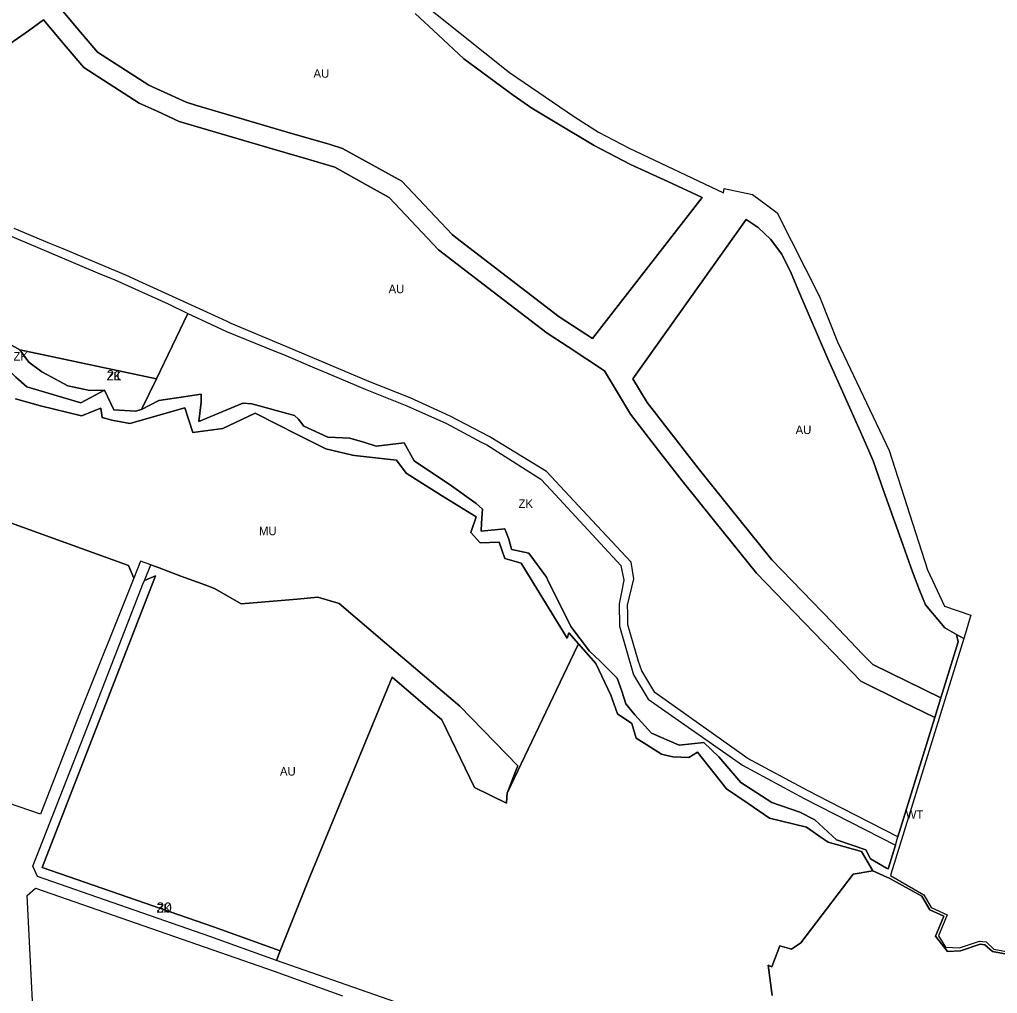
# Model space of a CAD drawing. Extents: x -522079 to -518833, y -1142398 to -1139961.
# Drawn here: x -520015 to -519439, y -1141329 to -1140756 of the extents above; entities that cross this region are included whole.
import ezdxf

# ---------------------------------------------------------------- set-up
doc = ezdxf.new("R2010")
doc.units = 0
for name, color, linetype in [('90640013', 7, 'Continuous'), ('90710013', 7, 'Continuous'), ('90710023', 7, 'Continuous'), ('90730013', 7, 'Continuous'), ('90750013', 7, 'Continuous'), ('90770013', 7, 'Continuous'), ('90830013', 7, 'Continuous'), ('ID_navrh', 7, 'Continuous')]:
    doc.layers.add(name, color=color, linetype=linetype)

msp = doc.modelspace()

# ---------------------------------------------------------------- linework, layer by layer
at = {"layer": '90640013'}
for points in [[(-520017.69, -1140966.19), (-520011.16, -1140971.75), (-519979.37, -1140981.19), (-519965.47, -1140973.69), (-519959.93, -1140985.31), (-519947.03, -1140986.05), (-519943.51, -1140985.08), (-519933.4, -1140979.93), (-519918.88, -1140977.69), (-519908.41, -1140976.07), (-519908.53, -1140980.82), (-519909.8, -1140992.3), (-519883.85, -1140981.36), (-519878.53, -1140981.83), (-519853.55, -1140988.6), (-519851.21, -1140990.81), (-519847.96, -1140994.97), (-519833.92, -1141001.35), (-519825.01, -1141001.81), (-519820.93, -1141002.11), (-519812.07, -1141004.64), (-519805.33, -1141006.69), (-519788.8, -1141004.86), (-519783.07, -1141015.31), (-519761.05, -1141030.01), (-519746.47, -1141040.52), (-519742.77, -1141043.74), (-519743.3, -1141051.84), (-519743.63, -1141056.81), (-519729.57, -1141055.46), (-519727.24, -1141061.4), (-519725.71, -1141067.43), (-519725.48, -1141067.48), (-519715.52, -1141069.7), (-519705.02, -1141083.87), (-519704.67, -1141084.75), (-519704.33, -1141085.64), (-519690.7, -1141113), (-519679.71, -1141127.39), (-519673.55, -1141133.3), (-519663.4, -1141143.35), (-519660.65, -1141151.03), (-519658.41, -1141158.35), (-519653.03, -1141164.92), (-519643.13, -1141175.65), (-519626.9, -1141182.72), (-519612.48, -1141181.23), (-519603.54, -1141189.56), (-519590.58, -1141204.82), (-519572.33, -1141216.46), (-519555.86, -1141222.18), (-519546.94, -1141226.78), (-519534.2, -1141238.58), (-519516.96, -1141244.4), (-519514.28, -1141249.74), (-519504.82, -1141255.11), (-519503.9, -1141255.56), (-519499.59, -1141241.58), (-519498.1, -1141236.79), (-519476.38, -1141166.58), (-519472.79, -1141154.97), (-519462.56, -1141121.92), (-519463.51, -1141117.64), (-519459.37, -1141120.07), (-519501.33, -1141255.67), (-519501.64, -1141256.67), (-519502.46, -1141259.44), (-519482.78, -1141270.88), (-519478.58, -1141278.28), (-519469.18, -1141282.65), (-519474.2, -1141295.1), (-519470.14, -1141301.74), (-519461.74, -1141302), (-519449.98, -1141298.09), (-519446.22, -1141298.48), (-519441.7, -1141302.87), (-519430.99, -1141304.77)], [(-519431.85, -1141306.14), (-519442.41, -1141304.27), (-519446.9, -1141300.29), (-519449.71, -1141299.98), (-519461.31, -1141303.85), (-519468.94, -1141304.33), (-519475.87, -1141295.24), (-519471.1, -1141283.41), (-519479.21, -1141279.64), (-519484.08, -1141271.62), (-519502.94, -1141261.24), (-519512.96, -1141256.69), (-519519.64, -1141245.38), (-519539.27, -1141239.84), (-519542.77, -1141237.45), (-519552.03, -1141231.12), (-519573.7, -1141225.77), (-519586.25, -1141217.21), (-519599.05, -1141208.49), (-519616.23, -1141186.99), (-519621.3, -1141190.09), (-519630.7, -1141189.62), (-519635, -1141188.59), (-519637.37, -1141188.02), (-519646.01, -1141182.51), (-519652.19, -1141178.57), (-519654.81, -1141169.94), (-519663.19, -1141164.28), (-519667.13, -1141153.28), (-519676.06, -1141134.77), (-519686.19, -1141123.12), (-519691.83, -1141116.63), (-519692.8, -1141119.72), (-519719.95, -1141075.61), (-519729.51, -1141072.8), (-519732.93, -1141063.24), (-519744.08, -1141063.56), (-519749.67, -1141057.47), (-519746.51, -1141048.43), (-519766.87, -1141035.85), (-519787.79, -1141022.58), (-519793.36, -1141014.98), (-519818.09, -1141012.26), (-519819.26, -1141011.99), (-519835.08, -1141008.27), (-519851.59, -1141000.07), (-519876.6, -1140987.29), (-519895.77, -1140996.31), (-519913.39, -1140998.68), (-519918.04, -1140984.12), (-519950.36, -1140993.42), (-519961.08, -1140991.39), (-519966.67, -1140989.91), (-519967.54, -1140984.38), (-519978.85, -1140988.86), (-520003.11, -1140982.94), (-520017.73, -1140978.78)]]:
    msp.add_lwpolyline(points, dxfattribs=at)
at = {"layer": '90710013'}
for points in [[(-519783.91, -1140740.96), (-519726.89, -1140786.75), (-519688.67, -1140812.79), (-519674.4, -1140821.79), (-519656.36, -1140831.22), (-519600.86, -1140857.49), (-519600.42, -1140854.95), (-519583.72, -1140858.5), (-519575.54, -1140864.6), (-519569.14, -1140869.38), (-519544.31, -1140918.54), (-519533.66, -1140945.39), (-519503.31, -1141009.21), (-519480.71, -1141079.48), (-519470.66, -1141100.87), (-519455.06, -1141106.14), (-519456.05, -1141109.33), (-519457.77, -1141114.91), (-519459.37, -1141120.07), (-519463.51, -1141117.64), (-519470.4, -1141113.6), (-519481.95, -1141100.21), (-519485.33, -1141091.52), (-519489.53, -1141080.75), (-519497.19, -1141059.15), (-519506.32, -1141033.4), (-519512.69, -1141015.45), (-519518.48, -1141001.84), (-519530.67, -1140974.63), (-519539.28, -1140955.41), (-519556.41, -1140915.6), (-519561.03, -1140904.86), (-519566.48, -1140893.71), (-519573.15, -1140884.93), (-519580.34, -1140878), (-519587.52, -1140873.31), (-519654.13, -1140967.02), (-519645.74, -1140981.03), (-519632.87, -1140997.67), (-519615.79, -1141019.75), (-519597.55, -1141042.38), (-519572.39, -1141073.59), (-519536.59, -1141110.65), (-519518.89, -1141129.28), (-519512.81, -1141135.27), (-519472.79, -1141154.97), (-519476.38, -1141166.58), (-519495.79, -1141157.02), (-519519.99, -1141145.11), (-519536.28, -1141128.25), (-519581.39, -1141081.54), (-519605.96, -1141051.06), (-519625.22, -1141027.17), (-519639.1, -1141009.23), (-519655.67, -1140987.81), (-519670.91, -1140962.34), (-519692.38, -1140948.3), (-519704.63, -1140940.29), (-519736.43, -1140915.9), (-519768.72, -1140891.13), (-519797.7, -1140860.26), (-519815.37, -1140850.5), (-519829.78, -1140842.53), (-519845.71, -1140837.84), (-519865.19, -1140832.11), (-519914.69, -1140817.53), (-519921.41, -1140815.55), (-519934.39, -1140809.6), (-519944.96, -1140804.75), (-519977.56, -1140783.82), (-519987.93, -1140771.54), (-520001.24, -1140755.77), (-520010.06, -1140762.16), (-520068.52, -1140802.68)], [(-519991.87, -1140748.27), (-519981.63, -1140760.4), (-519969.55, -1140774.7), (-519939.19, -1140794.19), (-519934.47, -1140796.36), (-519917.19, -1140804.28), (-519911.71, -1140805.9), (-519857.7, -1140821.8), (-519832.56, -1140829.21), (-519825.13, -1140831.39), (-519790.25, -1140850.67), (-519760.64, -1140882.2), (-519758.42, -1140883.91), (-519697.68, -1140930.5), (-519678.04, -1140943.34), (-519613.39, -1140860.38), (-519633.63, -1140850.83), (-519655.55, -1140840.89), (-519677.02, -1140829.78), (-519698.98, -1140816.54), (-519713.71, -1140807.66), (-519724.7, -1140800.07), (-519753.73, -1140778.67), (-519768.84, -1140764.57), (-519782.42, -1140752.04)]]:
    msp.add_lwpolyline(points, dxfattribs=at)
for points in [[(-519943.51, -1140985.08), (-519934.8, -1140967.08), (-519916.21, -1140928.63), (-519914.16, -1140929.63), (-519893.61, -1140939.25), (-519865.12, -1140950.76), (-519859.94, -1140952.86), (-519841.67, -1140960.58), (-519832.3, -1140964.53), (-519811.83, -1140973.18), (-519787.36, -1140982.97), (-519764.04, -1140993.49), (-519743.47, -1141004.35), (-519740.29, -1141006.03), (-519708.41, -1141026.12), (-519702.3, -1141032.7), (-519661.22, -1141076.98), (-519659.49, -1141085.69), (-519660.92, -1141092.62), (-519662.35, -1141099.54), (-519662.06, -1141112.71), (-519653.82, -1141141.35), (-519645.14, -1141155.67), (-519589.6, -1141194.6), (-519553.27, -1141214.2), (-519499.59, -1141241.58), (-519503.9, -1141255.56), (-519504.82, -1141255.11), (-519514.28, -1141249.74), (-519516.96, -1141244.4), (-519534.2, -1141238.58), (-519546.94, -1141226.78), (-519555.86, -1141222.18), (-519572.33, -1141216.46), (-519590.58, -1141204.82), (-519603.54, -1141189.56), (-519612.48, -1141181.23), (-519626.9, -1141182.72), (-519643.13, -1141175.65), (-519653.03, -1141164.92), (-519658.41, -1141158.35), (-519660.65, -1141151.03), (-519663.4, -1141143.35), (-519673.55, -1141133.3), (-519679.71, -1141127.39), (-519690.7, -1141113), (-519704.33, -1141085.64), (-519704.67, -1141084.75), (-519705.02, -1141083.87), (-519715.52, -1141069.7), (-519725.48, -1141067.48), (-519725.71, -1141067.43), (-519727.24, -1141061.4), (-519729.57, -1141055.46), (-519743.63, -1141056.81), (-519743.3, -1141051.84), (-519742.77, -1141043.74), (-519746.47, -1141040.52), (-519761.05, -1141030.01), (-519783.07, -1141015.31), (-519788.8, -1141004.86), (-519805.33, -1141006.69), (-519812.07, -1141004.64), (-519820.93, -1141002.11), (-519825.01, -1141001.81), (-519833.92, -1141001.35), (-519847.96, -1140994.97), (-519851.21, -1140990.81), (-519853.55, -1140988.6), (-519878.53, -1140981.83), (-519883.85, -1140981.36), (-519909.8, -1140992.3), (-519908.53, -1140980.82), (-519908.41, -1140976.07), (-519918.88, -1140977.69), (-519933.4, -1140979.93)], [(-520015.17, -1140949.95), (-520009.84, -1140957.29), (-520002.28, -1140962.91), (-519999.3, -1140964.63), (-519986.94, -1140971.3), (-519974.08, -1140974.02), (-519965.47, -1140973.69), (-519979.37, -1140981.19), (-520011.16, -1140971.75), (-520017.69, -1140966.19), (-520051.93, -1140931.48), (-520046.33, -1140932.29), (-520029.76, -1140941.98)]]:
    msp.add_lwpolyline(points, close=True, dxfattribs=at)
at = {"layer": '90710023'}
for points in [[(-520015.17, -1140949.95), (-519934.8, -1140967.08), (-519943.51, -1140985.08), (-519947.03, -1140986.05), (-519959.93, -1140985.31), (-519965.47, -1140973.69), (-519974.08, -1140974.02), (-519986.94, -1140971.3), (-519999.3, -1140964.63), (-520002.28, -1140962.91), (-520009.84, -1140957.29)], [(-519941.9, -1141085.78), (-519941.89, -1141085.78), (-519935.26, -1141083.16), (-520002.16, -1141254.73), (-519901.27, -1141289.8), (-519861.86, -1141303.89), (-519864.09, -1141309.46), (-519903.26, -1141295.46), (-520004.78, -1141260.17), (-520007.53, -1141254.06), (-519973.57, -1141167.53), (-519942.77, -1141088.03)]]:
    msp.add_lwpolyline(points, close=True, dxfattribs=at)
at = {"layer": '90730013'}
msp.add_lwpolyline([(-519572.25, -1141330.06), (-519574.58, -1141312.28), (-519572.4, -1141313.2), (-519567.64, -1141300.94), (-519560.68, -1141302.79), (-519555.19, -1141299.24), (-519524.47, -1141258.63), (-519512.96, -1141256.69), (-519502.94, -1141261.24), (-519484.08, -1141271.62), (-519479.21, -1141279.64), (-519471.1, -1141283.41), (-519475.87, -1141295.24), (-519468.94, -1141304.33), (-519461.31, -1141303.85), (-519449.71, -1141299.98), (-519446.9, -1141300.29), (-519442.41, -1141304.27), (-519431.85, -1141306.14)], dxfattribs=at)
at = {"layer": '90750013'}
for points in [[(-519782.42, -1140752.04), (-519768.84, -1140764.57), (-519753.73, -1140778.67), (-519724.7, -1140800.07), (-519713.71, -1140807.66), (-519698.98, -1140816.54), (-519677.02, -1140829.78), (-519655.55, -1140840.89), (-519633.63, -1140850.83), (-519613.39, -1140860.38), (-519678.04, -1140943.34), (-519697.68, -1140930.5), (-519758.42, -1140883.91), (-519760.64, -1140882.2), (-519790.25, -1140850.67), (-519825.13, -1140831.39), (-519832.56, -1140829.21), (-519857.7, -1140821.8), (-519911.71, -1140805.9), (-519917.19, -1140804.28), (-519934.47, -1140796.36), (-519939.19, -1140794.19), (-519969.55, -1140774.7), (-519981.63, -1140760.4), (-519991.87, -1140748.27)], [(-520068.52, -1140802.68), (-520010.06, -1140762.16), (-520001.24, -1140755.77), (-519987.93, -1140771.54), (-519977.56, -1140783.82), (-519944.96, -1140804.75), (-519934.39, -1140809.6), (-519921.41, -1140815.55), (-519914.69, -1140817.53), (-519865.19, -1140832.11), (-519845.71, -1140837.84), (-519829.78, -1140842.53), (-519815.37, -1140850.5), (-519797.7, -1140860.26), (-519768.72, -1140891.13), (-519736.43, -1140915.9), (-519704.63, -1140940.29), (-519692.38, -1140948.3), (-519670.91, -1140962.34), (-519655.67, -1140987.81), (-519639.1, -1141009.23), (-519625.22, -1141027.17), (-519605.96, -1141051.06), (-519581.39, -1141081.54), (-519536.28, -1141128.25), (-519519.99, -1141145.11), (-519495.79, -1141157.02), (-519476.38, -1141166.58), (-519498.1, -1141236.79), (-519538.78, -1141215.99), (-519550.99, -1141209.75), (-519586.93, -1141190.33), (-519588.4, -1141189.29), (-519641.2, -1141151.84), (-519648.88, -1141138.93), (-519650.97, -1141133.45), (-519657.08, -1141111.95), (-519657.23, -1141105.11), (-519657.33, -1141100.32), (-519653.67, -1141084.78), (-519655.12, -1141075.09), (-519678.16, -1141050.41), (-519704.97, -1141021.67), (-519737.76, -1141001.71), (-519738.84, -1141001.14), (-519761.84, -1140988.99), (-519785.4, -1140978.37), (-519792.75, -1140975.43), (-519809.71, -1140968.63), (-519858.03, -1140948.23), (-519890.83, -1140934.46), (-519893.61, -1140933.19), (-519907.29, -1140926.89), (-519923.13, -1140919.66), (-519943.08, -1140910.55), (-519952.82, -1140906.1), (-519990.79, -1140890.22), (-519997.49, -1140887.4), (-520018.57, -1140878.52)], [(-520005.29, -1141383.92), (-520010.89, -1141271.2), (-520005.98, -1141266.96), (-519865.42, -1141315.8), (-519825.24, -1141330.38)]]:
    msp.add_lwpolyline(points, dxfattribs=at)
for points in [[(-519463.51, -1141117.64), (-519462.56, -1141121.92), (-519472.79, -1141154.97), (-519512.81, -1141135.27), (-519518.89, -1141129.28), (-519536.59, -1141110.65), (-519572.39, -1141073.59), (-519597.55, -1141042.38), (-519615.79, -1141019.75), (-519632.87, -1140997.67), (-519645.74, -1140981.03), (-519654.13, -1140967.02), (-519587.52, -1140873.31), (-519580.34, -1140878), (-519573.15, -1140884.93), (-519566.48, -1140893.71), (-519561.03, -1140904.86), (-519556.41, -1140915.6), (-519539.28, -1140955.41), (-519530.67, -1140974.63), (-519518.48, -1141001.84), (-519512.69, -1141015.45), (-519506.32, -1141033.4), (-519497.19, -1141059.15), (-519489.53, -1141080.75), (-519485.33, -1141091.52), (-519481.95, -1141100.21), (-519470.4, -1141113.6)], [(-520194.38, -1141159.65), (-520235.62, -1141148.58), (-520200.4, -1141059.73), (-520205.51, -1141057.7), (-520170.88, -1140963.13), (-520079.53, -1141019.58), (-520032.33, -1141047.7), (-519951.21, -1141077.01), (-519948.1, -1141084.44), (-519980.55, -1141165.39), (-520002.99, -1141223.35), (-520143.75, -1141175.06)], [(-519941.9, -1141085.78), (-519938.17, -1141076.59), (-519933.25, -1141078.41), (-519920.33, -1141083.18), (-519905.71, -1141088.58), (-519900.64, -1141090.45), (-519884.82, -1141099.57), (-519851.93, -1141096.73), (-519839.81, -1141095.68), (-519827.19, -1141099.4), (-519800.19, -1141122.28), (-519756.03, -1141159.77), (-519721.93, -1141194.85), (-519723.28, -1141198.33), (-519728.23, -1141211.06), (-519728.39, -1141213.65), (-519728.58, -1141216.84), (-519747.5, -1141207.73), (-519766.69, -1141167.92), (-519795.94, -1141142.67), (-519845.38, -1141262.74), (-519861.86, -1141303.89), (-519901.27, -1141289.8), (-520002.16, -1141254.73), (-519935.26, -1141083.16), (-519941.89, -1141085.78)]]:
    msp.add_lwpolyline(points, close=True, dxfattribs=at)
at = {"layer": '90770013'}
msp.add_lwpolyline([(-519789.84, -1141335.36), (-519864.09, -1141309.46), (-519861.86, -1141303.89), (-519845.38, -1141262.74), (-519795.94, -1141142.67), (-519766.69, -1141167.92), (-519747.5, -1141207.73), (-519728.58, -1141216.84), (-519728.39, -1141213.65), (-519728.23, -1141211.06), (-519688.75, -1141128.51), (-519686.19, -1141123.12), (-519676.06, -1141134.77), (-519667.13, -1141153.28), (-519663.19, -1141164.28), (-519654.81, -1141169.94), (-519652.19, -1141178.57), (-519646.01, -1141182.51), (-519637.37, -1141188.02), (-519635, -1141188.59), (-519630.7, -1141189.62), (-519621.3, -1141190.09), (-519616.23, -1141186.99), (-519599.05, -1141208.49), (-519586.25, -1141217.21), (-519573.7, -1141225.77), (-519552.03, -1141231.12), (-519542.77, -1141237.45), (-519539.27, -1141239.84), (-519519.64, -1141245.38), (-519512.96, -1141256.69), (-519524.47, -1141258.63), (-519555.19, -1141299.24), (-519560.68, -1141302.79), (-519567.64, -1141300.94), (-519572.4, -1141313.2), (-519574.58, -1141312.28), (-519572.25, -1141330.06)], dxfattribs=at)
at = {"layer": '90830013'}
for points in [[(-520022.73, -1140882.19), (-519999.48, -1140892), (-519969.45, -1140904.62), (-519959.29, -1140908.89), (-519927.83, -1140922.94), (-519916.21, -1140928.63), (-519934.8, -1140967.08), (-520015.17, -1140949.95), (-520029.76, -1140941.98)], [(-520017.73, -1140978.78), (-520003.11, -1140982.94), (-519978.85, -1140988.86), (-519967.54, -1140984.38), (-519966.67, -1140989.91), (-519961.08, -1140991.39), (-519950.36, -1140993.42), (-519918.04, -1140984.12), (-519913.39, -1140998.68), (-519895.77, -1140996.31), (-519876.6, -1140987.29), (-519851.59, -1141000.07), (-519835.08, -1141008.27), (-519819.26, -1141011.99), (-519818.09, -1141012.26), (-519793.36, -1141014.98), (-519787.79, -1141022.58), (-519766.87, -1141035.85), (-519746.51, -1141048.43), (-519749.67, -1141057.47), (-519744.08, -1141063.56), (-519732.93, -1141063.24), (-519729.51, -1141072.8), (-519719.95, -1141075.61), (-519692.8, -1141119.72), (-519691.83, -1141116.63), (-519686.19, -1141123.12), (-519688.75, -1141128.51), (-519728.23, -1141211.06), (-519723.28, -1141198.33), (-519721.93, -1141194.85), (-519756.03, -1141159.77), (-519800.19, -1141122.28), (-519827.19, -1141099.4), (-519839.81, -1141095.68), (-519851.93, -1141096.73), (-519884.82, -1141099.57), (-519900.64, -1141090.45), (-519905.71, -1141088.58), (-519920.33, -1141083.18), (-519933.25, -1141078.41), (-519938.17, -1141076.59), (-519944.08, -1141074.41), (-519948.1, -1141084.44), (-519951.21, -1141077.01), (-520032.33, -1141047.7)]]:
    msp.add_lwpolyline(points, dxfattribs=at)

# ---------------------------------------------------------------- texts
at = {"layer": '90640013'}
msp.add_text('WT', height=5, rotation=0, dxfattribs=at).set_placement((-519493.48, -1141226.079))
at = {"layer": '90710013'}
for rotation, p in [(360, (-520018.973, -1140956.335)), (0, (-519721.55, -1141043.098))]:
    msp.add_text('ZK', height=5, rotation=rotation, dxfattribs=at).set_placement(p)
at = {"layer": '90710023'}
for p in [(-519964.15, -1140968), (-519934.695, -1141281.357)]:
    msp.add_text('ZK', height=5, rotation=0, dxfattribs=at).set_placement(p)
at = {"layer": '90750013'}
for rotation, p in [(360, (-519842.301, -1140789.82)), (0, (-519798.075, -1140916.674)), (0, (-519558.345, -1140999.616)), (360, (-519862.045, -1141200.714))]:
    msp.add_text('AU', height=5, rotation=rotation, dxfattribs=at).set_placement(p)
at = {"layer": '90830013'}
msp.add_text('MU', height=5, rotation=0, dxfattribs=at).set_placement((-519874.393, -1141059.145))
at = {"layer": 'ID_navrh'}
for s, rotation, p in [('21', 360, (-519964.15, -1140968)), ('30', 0, (-519934.695, -1141281.357))]:
    msp.add_text(s, height=6, rotation=rotation, dxfattribs=at).set_placement(p)

doc.saveas('drawing.dxf')
